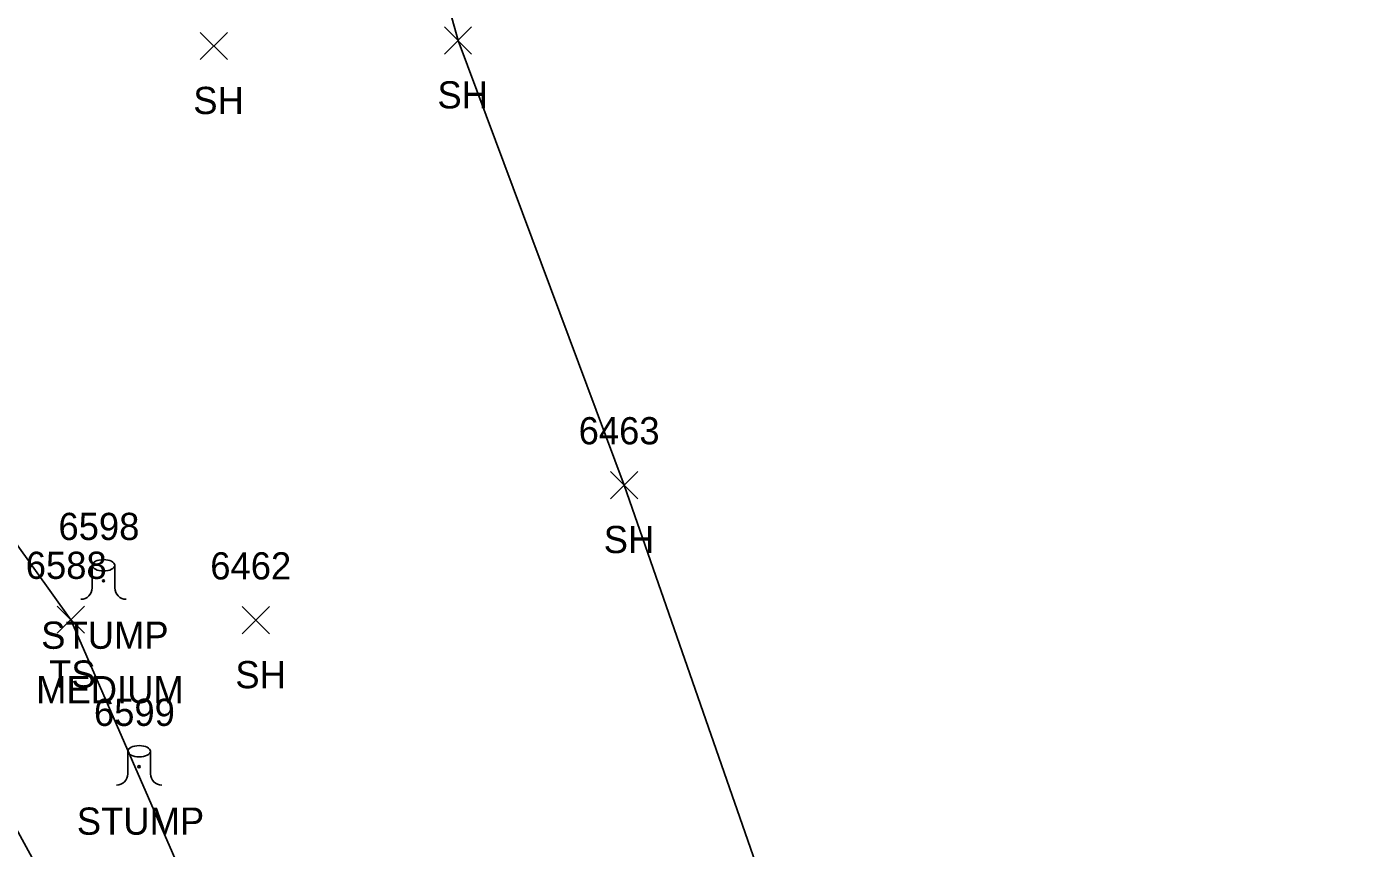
# Model space of a CAD drawing. Extents: x 1769141 to 1770911, y 735471 to 741449.
# Drawn here: x 1770229.3 to 1770326.7, y 740871.5 to 740932 of the extents above; entities that cross this region are included whole.
import ezdxf

# ---------------------------------------------------------------- set-up
doc = ezdxf.new("R2010")
doc.units = 0
for name, color, linetype in [('L_A', 7, 'Continuous'), ('L_C', 7, 'Continuous'), ('L_I', 7, 'Continuous'), ('L_TIC', 7, 'Continuous'), ('LELB', 7, 'Continuous'), ('LSOGP', 7, 'Continuous'), ('LTS', 7, 'Continuous')]:
    doc.layers.add(name, color=color, linetype=linetype)

msp = doc.modelspace()

# ---------------------------------------------------------------- linework, layer by layer
at = {"layer": 'L_TIC'}
for points in [[(1770242.072, 740929.54), (1770244.072, 740931.54)], [(1770244.072, 740929.54), (1770242.072, 740931.54)], [(1770260.014, 740929.952), (1770262.014, 740931.952)], [(1770262.014, 740929.952), (1770260.014, 740931.952)], [(1770272.233, 740897.25), (1770274.233, 740899.25)], [(1770274.233, 740897.25), (1770272.233, 740899.25)], [(1770231.554, 740887.353), (1770233.554, 740889.353)], [(1770233.554, 740887.353), (1770231.554, 740889.353)], [(1770245.161, 740887.312), (1770247.161, 740889.312)], [(1770247.161, 740887.312), (1770245.161, 740889.312)]]:
    msp.add_lwpolyline(points, dxfattribs=at)
at = {"layer": 'LELB'}
for points in [[(1770206.325, 740923.12), (1770218.826, 740907.514), (1770232.554, 740888.353), (1770243.383, 740863.511), (1770259.878, 740856.695), (1770267.465, 740842.916), (1770277.815, 740826.928)], [(1770240.242, 740844.356), (1770238.589, 740848.809), (1770239.598, 740852.724), (1770226.756, 740876.232), (1770210.967, 740892.635), (1770189.956, 740913.809)]]:
    msp.add_lwpolyline(points, dxfattribs=at)
at = {"layer": 'LSOGP'}
msp.add_lwpolyline([(1770326.749, 740777.797), (1770321.91, 740797.701), (1770321.183, 740802.043), (1770319.128, 740806.628), (1770297.879, 740801.102), (1770296.632, 740805.083), (1770294.139, 740814.916), (1770293.756, 740817.035), (1770290.358, 740830.172), (1770289.843, 740831.832), (1770287.378, 740841.622), (1770286.406, 740845.581), (1770294.231, 740847.568), (1770289.463, 740851.557), (1770273.233, 740898.25), (1770261.014, 740930.952), (1770256.423, 740947.489)], dxfattribs=at)
at = {"layer": 'LTS'}
for p, q in [((1770234.129, 740892.352), (1770234.129, 740890.686)), ((1770235.796, 740892.186), (1770235.796, 740892.352)), ((1770235.796, 740892.352), (1770235.796, 740890.686)), ((1770234.962, 740891.21), (1770234.962, 740891.21)), ((1770234.962, 740891.21), (1770234.962, 740891.21)), ((1770234.962, 740891.186), (1770234.962, 740891.186)), ((1770236.745, 740878.68), (1770236.745, 740877.013)), ((1770238.412, 740878.513), (1770238.412, 740878.68)), ((1770238.412, 740878.68), (1770238.412, 740877.013)), ((1770237.578, 740877.538), (1770237.578, 740877.538)), ((1770237.578, 740877.538), (1770237.578, 740877.538)), ((1770237.578, 740877.513), (1770237.578, 740877.513))]:
    msp.add_line(p, q, dxfattribs=at)
for centre in [(1770234.962, 740891.21), (1770237.578, 740877.538)]:
    msp.add_circle(centre, 0.0833, dxfattribs=at)
for centre, start, end in [((1770233.296, 740890.686), 270, 360), ((1770236.629, 740890.686), 180, 270), ((1770235.912, 740877.013), 270, 360), ((1770239.245, 740877.013), 180, 270)]:
    msp.add_arc(centre, 0.833, start, end, dxfattribs=at)
for centre in [(1770234.962, 740892.352), (1770237.578, 740878.68)]:
    msp.add_ellipse(centre, major_axis=(-0.833, 0), ratio=0.5, dxfattribs=at)

# ---------------------------------------------------------------- texts
at = {"layer": 'L_A'}
for s, p in [('SH', (1770241.56, 740925.54)), ('SH', (1770259.502, 740925.952)), ('SH', (1770271.721, 740893.25)), ('STUMP', (1770230.383, 740886.212)), ('TS', (1770230.963, 740883.353)), ('SH', (1770244.649, 740883.312)), ('STUMP', (1770232.999, 740872.54))]:
    msp.add_text(s, height=2, dxfattribs=at).set_placement(p)
at = {"layer": 'L_C'}
msp.add_text('MEDIUM', height=2, dxfattribs=at).set_placement((1770230.013, 740882.212))
at = {"layer": 'L_I'}
for s, p in [('6463', (1770269.879, 740901.25)), ('6598', (1770231.651, 740894.212)), ('6588', (1770229.247, 740891.353)), ('6462', (1770242.807, 740891.312)), ('6599', (1770234.259, 740880.54))]:
    msp.add_text(s, height=2, dxfattribs=at).set_placement(p)

doc.saveas('drawing.dxf')
